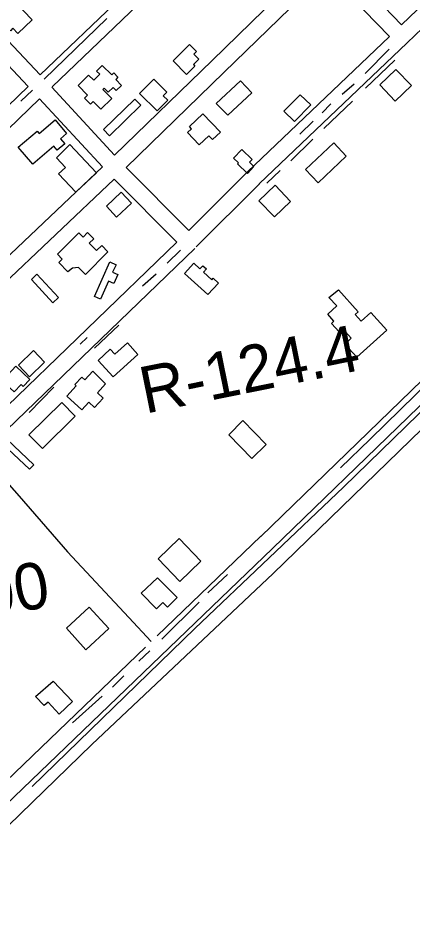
# Model space of a CAD drawing. Extents: x 3568792 to 3606828, y 529143 to 554785.
# Drawn here: x 3580485 to 3581187, y 536853 to 538456 of the extents above; entities that cross this region are included whole.
import ezdxf

# ---------------------------------------------------------------- set-up
doc = ezdxf.new("R2010")
doc.units = 0
for name, color, linetype in [('V-BLDG-OTLN', 7, 'Continuous'), ('V-DTCH-CNTR', 7, 'Continuous'), ('V-RIVR-RANG-IDEN', 7, 'Continuous'), ('V-ROAD-CNTR', 7, 'Continuous'), ('V-TOPO-SHOR', 7, 'Continuous')]:
    doc.layers.add(name, color=color, linetype=linetype)

msp = doc.modelspace()

# ---------------------------------------------------------------- linework, layer by layer
at = {"layer": 'V-BLDG-OTLN'}
for points in [[(3580436.8, 538477.9), (3580470.3, 538513.2), (3580488.9, 538495.5), (3580479.1, 538485.1), (3580510.1, 538452.7), (3580484.7, 538428.5), (3580475.7, 538438), (3580471.1, 538433.6), (3580457.7, 538447.6), (3580462.9, 538452.6)], [(3580761.3, 538379.9), (3580790.5, 538408.8), (3580802.8, 538396.3), (3580798.1, 538391.6), (3580807, 538382.6), (3580797.4, 538373.1), (3580800.1, 538370.3), (3580785.1, 538355.5)], [(3580632.2, 538293.5), (3580618.5, 538307.2), (3580614.1, 538302.9), (3580603.4, 538313.6), (3580608.6, 538318.9), (3580591.7, 538335.8), (3580610.5, 538354.6), (3580619.6, 538345.4), (3580630.4, 538356.2), (3580624.9, 538361.7), (3580635, 538371.7), (3580651.9, 538354.8), (3580655.3, 538358.3), (3580662.7, 538350.6), (3580658.8, 538346.6), (3580668.9, 538336.1), (3580659.5, 538327), (3580654.2, 538332.4), (3580645.6, 538324), (3580638.5, 538331.3), (3580636.1, 538329), (3580651.7, 538313)], [(3581158.2, 538364.6), (3581129.3, 538337), (3581156.9, 538308), (3581185.8, 538335.7)], [(3580732.9, 538290.7), (3580701.3, 538321.8), (3580726.5, 538347.4), (3580749.9, 538324.3), (3580743.4, 538317.7), (3580751.5, 538309.7)], [(3580838.1, 538304), (3580881.1, 538344.2), (3580901.2, 538322.8), (3580858.7, 538283)], [(3581006.6, 538301.2), (3580977.3, 538271.9), (3580958.7, 538290.4), (3580987.4, 538319.1)], [(3580637.2, 538257.3), (3580692.7, 538311.8), (3580703.4, 538300.9), (3580647.9, 538246.4)], [(3580510.9, 538195.6), (3580485.3, 538226.2), (3580519, 538254.4), (3580522.2, 538250.7), (3580550.9, 538274.7), (3580571.2, 538250.4), (3580560.3, 538241.2), (3580568, 538232), (3580554.4, 538220.7), (3580548.7, 538227.6)], [(3580814.3, 538285.7), (3580845.4, 538252.7), (3580831.5, 538239.5), (3580825, 538246.4), (3580807.7, 538230), (3580786.7, 538252.2), (3580793.9, 538259), (3580790.1, 538263)], [(3580577.3, 538230.8), (3580624.4, 538180.5), (3580587.7, 538146.1), (3580557.1, 538178.8), (3580569.1, 538190), (3580553.2, 538207)], [(3580893.9, 538178.9), (3580876, 538196.3), (3580877.6, 538197.9), (3580868.6, 538206.7), (3580883.4, 538221.8), (3580901.8, 538203.8), (3580897.3, 538199.2), (3580905, 538191.7)], [(3580997.2, 538186.4), (3581047.3, 538233.7), (3581069.8, 538209.9), (3581019.9, 538162.8)], [(3580943, 538158.3), (3580914.1, 538130.7), (3580941.7, 538101.8), (3580970.6, 538129.4)], [(3580642.2, 538121.1), (3580668.4, 538145.9), (3580686.9, 538126.3), (3580660.5, 538101.4)], [(3580555, 538035.2), (3580593, 538073.7), (3580600.8, 538065.9), (3580608.7, 538073.9), (3580619.8, 538063), (3580611.8, 538054.9), (3580624.9, 538041.9), (3580633.9, 538051), (3580645.1, 538039.8), (3580604.9, 537999.5), (3580592.7, 538011.6), (3580582, 538010.5), (3580573.3, 538003.7), (3580557.3, 538020.6), (3580563.2, 538026.5)], [(3580621.1, 537960.3), (3580648.2, 538021.7), (3580659.4, 538016.7), (3580653.4, 538003.2), (3580662.6, 537999.1), (3580655.5, 537983.2), (3580646, 537987.4), (3580631.7, 537955.1)], [(3580823.2, 537963.4), (3580781.5, 538001), (3580797.9, 538019.2), (3580809, 538009.2), (3580814.1, 538014.8), (3580820.4, 538009.1), (3580815, 538003.2), (3580830.2, 537989.6), (3580832.7, 537992.4), (3580842.1, 537983.9)], [(3580518.5, 537999.7), (3580557, 537958), (3580547, 537948.8), (3580508.7, 537990.3)], [(3581055.9, 537971.7), (3581091.1, 537932.8), (3581085.7, 537928), (3581096.3, 537916.3), (3581113.2, 537931.5), (3581141.7, 537900), (3581088.5, 537851.7), (3581067.1, 537875.3), (3581078.6, 537885.8), (3581063.5, 537902.5), (3581057.3, 537896.9), (3581043.5, 537912.2), (3581047.7, 537916.1), (3581036.6, 537928.5), (3581052.6, 537943.1), (3581038.7, 537958.5)], [(3580698, 537856.5), (3580654.5, 537816.7), (3580627.6, 537846.1), (3580649.2, 537865.9), (3580657.3, 537857), (3580679.6, 537877.4)], [(3580485.4, 537837.6), (3580512.4, 537863.6), (3580532.1, 537843.3), (3580505, 537817.1)], [(3580459.3, 537812.9), (3580480.8, 537835.7), (3580505.8, 537812.3), (3580494, 537799.8), (3580490.1, 537803.5), (3580477.7, 537790.3), (3580463.3, 537804), (3580465.3, 537806.1)], [(3580640.8, 537804.3), (3580626.2, 537788.3), (3580636.5, 537778.9), (3580621.3, 537762.2), (3580611, 537771.6), (3580598.5, 537758), (3580571.8, 537782.4), (3580588.6, 537800.8), (3580586.2, 537803), (3580598.5, 537816.4), (3580603.9, 537811.4), (3580618.2, 537827)], [(3580586.4, 537746.7), (3580528.2, 537689.5), (3580504.3, 537713.8), (3580562.8, 537771.4)], [(3580885.6, 537739.3), (3580927.2, 537696.3), (3580901.4, 537671.3), (3580860.5, 537713.6)], [(3580465.2, 537705), (3580512.9, 537660.1), (3580505.4, 537652.1), (3580457.7, 537697)], [(3580734.6, 537492.7), (3580772.1, 537528.8), (3580810.7, 537488.7), (3580772.9, 537452.4)], [(3580733.2, 537458.8), (3580768.4, 537423.6), (3580751.2, 537406.4), (3580743, 537414.7), (3580731.8, 537403.5), (3580704.1, 537431.2)], [(3580571.2, 537369.2), (3580611.5, 537406.7), (3580646.7, 537368.8), (3580605.9, 537330.8)], [(3580547.4, 537274.9), (3580581.7, 537238.3), (3580558.1, 537216.2), (3580538.2, 537237.4), (3580531.5, 537231.1), (3580516.1, 537247.6)]]:
    msp.add_lwpolyline(points, close=True, dxfattribs=at)
at = {"layer": 'V-DTCH-CNTR'}
msp.add_lwpolyline([(3581743, 537750.6), (3581648.6, 537905.1), (3581552.6, 538067.7), (3581265.5, 537783.1), (3580939.5, 537466.5), (3580616.5, 537161.8), (3580274.6, 536830.3), (3580101.1, 536657.5), (3580153.1, 536594.7), (3580038.4, 536485.8), (3579962.5, 536549.1), (3579802, 536396.8), (3579619.1, 536225.5), (3579445.1, 536055.2), (3579345.4, 535955.3), (3579344.6, 535829.1)], dxfattribs=at)
at = {"layer": 'V-ROAD-CNTR'}
for p, q in [((3580524.5, 538354.8), (3580881.8, 538697)), ((3580545.9, 538333.8), (3580902.6, 538675.4)), ((3581014.9, 538559.7), (3580830.5, 538380.6)), ((3581168.2, 538444), (3581057, 538559.3)), ((3581035.8, 538538.1), (3580851.4, 538359.1)), ((3581146.6, 538423.2), (3581035.8, 538538.1)), ((3580524.5, 538354.8), (3580410.6, 538475.5)), ((3580502.9, 538334.1), (3580389.1, 538454.6)), ((3581146.5, 538423.2), (3580893.9, 538182.2)), ((3580830.5, 538380.6), (3580656.8, 538211.6)), ((3580851.4, 538359.1), (3580677.5, 538190)), ((3580127.5, 537973.3), (3580502.9, 538334.1)), ((3580656.8, 538211.6), (3580545, 538332.9)), ((3580155.7, 537958.8), (3580523.3, 538312.1)), ((3580635.2, 538190.9), (3580523.3, 538312.1)), ((3580917.4, 537532.7), (3581681.3, 538272.3)), ((3580635.2, 538190.9), (3580272.1, 537846.7)), ((3580655.9, 538169.2), (3580293.8, 537825.8)), ((3580767.8, 538056.7), (3580655.9, 538169.2)), ((3580767.8, 538056.7), (3580411.1, 537712.8))]:
    msp.add_line(p, q, dxfattribs=at)
for points in [[(3580938.2, 537511.2), (3581663.4, 538213.2), (3581711.4, 538262), (3582051.3, 538582.5), (3582436.7, 538953.5), (3582639.8, 539148.6), (3582821.3, 539321.6), (3582927.1, 539429.2)], [(3581307.9, 538578), (3581168.2, 538444)], [(3581328.7, 538556.4), (3581178.3, 538412), (3580914.7, 538160.5)], [(3580893.7, 538181.9), (3580789.2, 538077.7), (3580677.5, 538190)], [(3580914.9, 538160.7), (3580802.5, 538048.5)], [(3580799.6, 538045.6), (3580431, 537690.4)], [(3580419.8, 537679.5), (3580486.7, 537604.5), (3580573.1, 537505.1), (3580682, 537388.3), (3580722.3, 537345.3)], [(3580917.4, 537532.8), (3580733, 537355.6)], [(3580938.2, 537511.1), (3579971.2, 536582.1)], [(3580712.1, 537335.5), (3579889.3, 536545)]]:
    msp.add_lwpolyline(points, dxfattribs=at)
at = {"layer": 'V-TOPO-SHOR'}
for p, q in [((3580531.6, 538347.1), (3580643.2, 538455.1)), ((3581103.5, 538357.2), (3581146.4, 538400.9)), ((3581104.2, 538331.3), (3581156.1, 538380.9)), ((3581062.5, 538320.3), (3581083.9, 538339)), ((3580489.6, 538307.9), (3580510.6, 538327.5)), ((3581027, 538287.5), (3581042, 538303)), ((3581029.9, 538259.3), (3581081, 538308)), ((3580986.9, 538249.3), (3581010.6, 538272.5)), ((3580970.7, 538201.9), (3581009.9, 538240.6)), ((3580928.3, 538161.8), (3580952, 538184.2)), ((3580750.4, 538019.3), (3580774.1, 538042.5)), ((3580706.7, 537979.2), (3580730.8, 538000.6)), ((3580621.3, 537867.9), (3580664.4, 537909.1)), ((3580595.5, 537875.3), (3580607.8, 537886.7)), ((3580504.8, 537753.3), (3580548.8, 537798.2)), ((3580823.3, 537432.1), (3580858.3, 537464.5)), ((3580741.2, 537349.7), (3580807.3, 537415.7)), ((3580700.2, 537310.1), (3580719.4, 537328.7)), ((3580652.9, 537264.1), (3580673.4, 537284.1)), ((3580581.8, 537200.3), (3580634.6, 537247.7))]:
    msp.add_line(p, q, dxfattribs=at)
for points in [[(3580510, 537087.1), (3580799.8, 537368.5), (3581064.9, 537620.6), (3581331.3, 537880), (3581582.5, 538122.1)], [(3581059.7, 537654.8), (3581112.1, 537705.9), (3581219.7, 537811.1)]]:
    msp.add_lwpolyline(points, dxfattribs=at)

# ---------------------------------------------------------------- texts
at = {"layer": 'V-RIVR-RANG-IDEN'}
for s, rotation, p in [('R-124.4', 11.4465, (3580711.3, 537751)), ('D-100', 9.7793, (3580247.6, 537356.7))]:
    msp.add_text(s, height=83, rotation=rotation, dxfattribs=at).set_placement(p)

doc.saveas('drawing.dxf')
